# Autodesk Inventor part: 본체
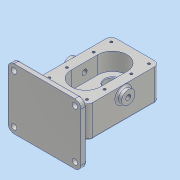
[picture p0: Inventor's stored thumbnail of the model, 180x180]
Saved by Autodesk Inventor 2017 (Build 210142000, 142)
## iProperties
Part Number: 본체
Material: 알루미늄 6061
Document SubType Name: Modeling
Designer: MRC
Mass: 1472.54 g
Surface Area: 818.394 cm^2
Volume: 545.387 cm^3
Density: 2.7 g/cm^3
Appearance: 알루미늄 - 평지
Author: MRC
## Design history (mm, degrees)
sketch "스케치1"
  geometry: L1 (-40, -60)-(40, -60); L2 (40, -60)-(40, 60); L3 (40, 60)-(-40, 60); L4 (-40, 60)-(-40, -60); 3 further points
  constraints: 8 end point, 2 midpoint, 2 parallel, 1 horizontal, 1 horizontal alignment, 1 perpendicular, 1 vertical alignment
  dimensions: "d0" = 80 distance of L3.end L2.end; "d1" = 120 distance of L2.end L1.end
extrude "돌출1" new body sketch "스케치1" distance "d2" = 14; taper "d3" = 0 deg; dims "d5" = 39, "d6" = 0
fillet "모깎기1" dims "d4" = 9
sketch "스케치2"
  geometry: L1 (0, -22)-(0, 22); L2 (-24, -22)-(-24, 22); L3 (24, 22)-(24, -22); A1 r 24 centre (0, -22) between (-24, -22) and (24, -22); A2 r 24 centre (0, 22) between (24, 22) and (-24, 22); 2 further points
  constraints: 8 end point, 4 point on circle, 4 tangent, 2 centre point, 1 coincident, 1 midpoint, 1 parallel, 1 vertical
  dimensions: "d7" = 24 radius of A2; "d8" = 44 distance of L1.start L1.end
extrude "돌출2" cut sketch "스케치2" distance "d9" = 29; taper "d10" = 0 deg
sketch "스케치4"
  geometry: C1 r 19 at (0, 22); 1 further point
  constraints: 1 centre point, 1 vertical alignment
  dimensions: "d11" = 38 diameter of C1; "d12" = 22 distance of point (0, 0) C1.centre
extrude "돌출3" join sketch "스케치4" distance "d13" = 17; taper "d14" = 0 deg
sketch "스케치5"
  geometry: C1 r 12.5 at (0, 22); A1 r 24 centre (0, 22) between (24, 22) and (-24, 22) reference; 1 further point
  constraints: 1 centre point, 1 coincident
  dimensions: "d15" = 25 diameter of C1
extrude "돌출4" cut sketch "스케치5" distance "d16" = 15; taper "d17" = 0 deg
sketch "스케치6"
  geometry: C1 r 12.5 at (0, 0) reference; C2 r 8.5 at (0, 0); 1 further point
  constraints: 1 centre point, 1 coincident
  dimensions: "d18" = 17 diameter of C2
extrude "돌출5" cut sketch "스케치6" stored distance "d19" = 15; taper "d20" = 0 deg
sketch "스케치7"
  geometry: C1 r 8.5 at (0, 0) reference; C2 r 19 at (0, 0) reference; C3 r 14 at (0, 0); 1 further point
  constraints: 1 centre point, 1 coincident
  dimensions: "d21" = 28 diameter of C3
extrude "돌출6" cut sketch "스케치7" distance "d22" = 7.3; taper "d23" = 0 deg
sketch "스케치8"
  geometry: C1 r 12.5 at (0, -22); A1 r 24 centre (0, -22) between (-24, -22) and (24, -22) reference; 1 further point
  constraints: 1 centre point, 1 coincident
  dimensions: "d24" = 25 diameter of C1
extrude "돌출7" cut sketch "스케치8" distance "d25" = 15; taper "d26" = 0 deg
sketch "스케치9"
  geometry: A1 r 24 centre (0, 22) between (24, 22) and (-24, 22) reference; 9 further points
  constraints: 6 vertical alignment, 3 horizontal alignment
  dimensions: "d27" = 62 distance of point (31, 51) point (-31, 51); "d28" = 29 distance of point (-31, 51) point (-31, 22); "d29" = 44 distance of point (-31, -22) point (-31, 22); "d30" = 29 distance of point (-31, -51) point (-31, -22); "d31" = 22 vertical distance of point (0, 0) point (-31, -22); "d32" = 31 horizontal distance of A1.centre point (-31, 51); "d33" = 29 distance of point (31, 51) point (31, 22)
hole "구멍1" sketch "스케치9" at (-31, 51), (-31, 22), (-31, -22), (-31, -51), (31, -51), (31, -22), (31, 22), (31, 51) diameter "d34" = 4.134; stored, may be unused: countersink angle "d38" = 90 deg, drill point angle "d40" = 118 deg; dims "d35" = 10, "d36" = 4, "d37" = 2, "d39" = 12
sketch "스케치10"
  geometry: L1 (-90, 44)-(-80, 44); L2 (-80, 44)-(-80, -56); L3 (-80, -56)-(-90, -56); L4 (-90, -56)-(-90, 44); L5 (36, -56)-(8, -56) reference; L6 (-46, 14)-(-46, -15) reference; L7 (-46, -15)-(-34.5, -15) reference; L8 (-34.5, -15)-(-34.5, -30) reference; L9 (-34.5, -30)-(-9.5, -30) reference; L10 (-9.5, -30)-(-9.5, -15) reference; L11 (-9.5, -15)-(9.5, -15) reference; L12 (9.5, -15)-(9.5, -30) reference; L13 (9.5, -30)-(13.5, -30) reference; L14 (13.5, -30)-(13.5, -48.7) reference; L15 (13.5, -48.7)-(8, -48.7) reference; L16 (8, -48.7)-(8, -56) reference; L17 (8, -56)-(3, -56) reference; L18 (3, -56)-(3, -39) reference; L19 (3, -39)-(-60, -39) reference; L20 (-60, -39)-(-60, 14) reference; L21 (-60, 14)-(-46, 14) reference; L22 (46, -15)-(46, 14) reference; L23 (46, 14)-(60, 14) reference; L24 (60, 14)-(60, -39) reference; L25 (60, -39)-(41, -39) reference; L26 (41, -39)-(41, -56) reference; L27 (41, -56)-(36, -56) reference; L28 (36, -56)-(36, -48.7) reference; L29 (36, -48.7)-(30.5, -48.7) reference; L30 (30.5, -48.7)-(30.5, -30) reference; L31 (30.5, -30)-(34.5, -30) reference; L32 (34.5, -30)-(34.5, -15) reference; L33 (34.5, -15)-(46, -15) reference; 1 further point
  constraints: 8 end point, 2 parallel, 1 horizontal, 1 perpendicular, 1 point on line
  dimensions: "d41" = 10 distance of L2.end L3.end; "d42" = 90 distance from line of point (0, 0) L4; "d43" = 100 distance of L3.end L1.start
extrude "돌출8" join sketch "스케치10" stored distance "d44" = 120; taper "d45" = 0 deg
sketch "스케치11"
  geometry: L1 (-80, 44)-(-80, -56) reference; L2 (-80, -39)-(-60, -27.453); L3 (-80, 14)-(-60, 2.453); L4 (-80, -56)-(-90, -56) reference; L5 (-46, 14)-(-46, -15) reference; L6 (-46, -15)-(-34.5, -15) reference; L7 (-34.5, -15)-(-34.5, -30) reference; L8 (-34.5, -30)-(-9.5, -30) reference; L9 (-9.5, -30)-(-9.5, -15) reference; L10 (-9.5, -15)-(9.5, -15) reference; L11 (9.5, -15)-(9.5, -30) reference; L12 (9.5, -30)-(13.5, -30) reference; L13 (13.5, -30)-(13.5, -48.7) reference; L14 (13.5, -48.7)-(8, -48.7) reference; L15 (8, -48.7)-(8, -56) reference; L16 (8, -56)-(3, -56) reference; L17 (3, -56)-(3, -39) reference; L18 (3, -39)-(-60, -39) reference; L19 (-60, -39)-(-60, 14) reference; L20 (-60, 14)-(-46, 14) reference; L21 (46, -15)-(46, 14) reference; L22 (46, 14)-(60, 14) reference; L23 (60, 14)-(60, -39) reference; L24 (60, -39)-(41, -39) reference; L25 (41, -39)-(41, -56) reference; L26 (41, -56)-(36, -56) reference; L27 (36, -56)-(36, -48.7) reference; L28 (36, -48.7)-(30.5, -48.7) reference; L29 (30.5, -48.7)-(30.5, -30) reference; L30 (30.5, -30)-(34.5, -30) reference; L31 (34.5, -30)-(34.5, -15) reference; L32 (34.5, -15)-(46, -15) reference; L33 (-80, 44)-(-80, -56) reference; L34 (-80, -56)-(-90, -56) reference; L35 (-90, -56)-(-90, 44) reference; L36 (-90, 44)-(-80, 44) reference; L37 (-80, 14)-(-80, -39); L38 (-60, -27.453)-(-60, 2.453); 1 further point
  constraints: 8 end point, 4 point on line, 2 collinear
  dimensions: "d46" = 53 distance of L2.start L3.start; "d47" = 17 distance from line of L4 L2.start; "d48" = 60 deg angle of L1 L2; "d49" = 60 deg angle of L1 L3
extrude "돌출9" join sketch "스케치11" stored distance "d50" = 48; taper "d51" = 0 deg
fillet "모깎기2" dims "d52" = 10
sketch "스케치12"
  geometry: C1 r 4.5 at (100, -10); C2 r 4.5 at (100, -90); C3 r 4.5 at (0, -90); C4 r 4.5 at (0, -10); A1 r 10 centre (100, -10) between (110, -10) and (100, 0) reference; A2 r 10 centre (0, -10) between (0, 0) and (-10, -10) reference; A3 r 10 centre (0, -90) between (-10, -90) and (0, -100) reference; A4 r 10 centre (100, -90) between (100, -100) and (110, -90) reference; 1 further point
  constraints: 4 centre point, 4 coincident
  dimensions: "d53" = 9 diameter of C1; "d54" = 9 diameter of C2; "d55" = 9 diameter of C3; "d56" = 9 diameter of C4
extrude "돌출10" cut sketch "스케치12" stored distance "d57" = 48; taper "d58" = 0 deg
sketch "스케치13"
  geometry: C1 r 11 at (-39, 51); 1 further point
  constraints: 1 centre point, 1 coincident
  dimensions: "d59" = 22 diameter of C1
extrude "돌출11" join sketch "스케치13" distance "d60" = 8; taper "d61" = 0 deg
sketch "스케치14"
  geometry: C1 r 11 at (0, 0) reference; 1 further point
  constraints: 1 coincident
hole "구멍2" sketch "스케치14" at (0, 0) diameter "d62" = 8.376; stored, may be unused: countersink angle "d66" = 90 deg, drill point angle "d68" = 118 deg; dims "d63" = 30, "d64" = 4, "d65" = 2, "d67" = 27.3
fillet "모깎기3" dims "d69" = 3
fillet "모깎기4" dims "d70" = 3
chamfer "모따기1" distance "d71" = 1; stored, may be unused: second distance "d72" = 2, angle "d73" = 45 deg
chamfer "모따기2" distance "d74" = 0.7; stored, may be unused: second distance "d75" = 2, angle "d76" = 30 deg
fillet "모깎기5" dims "d77" = 0.5
sketch "스케치15"
  geometry: L1 (0, -3)-(100, -3) reference; L2 (-10, 87)-(-10, 7) reference; 2 further points
  constraints: 1 other
  dimensions: "d78" = 10 distance from line of L1 point (50, 7); "d82" = 60 distance from line of L2 point (50, 7)
feature "엠보싱1" sketch "스케치15" dims "d0" = 80, "d1" = 120, "d79" = 0.5, "d80" = 0
fillet "모깎기6" dims "d81" = 3
node "솔리드1"
mirror "미러1"
node "절단 모서리 투영1"
node "절단 모서리 투영2"
